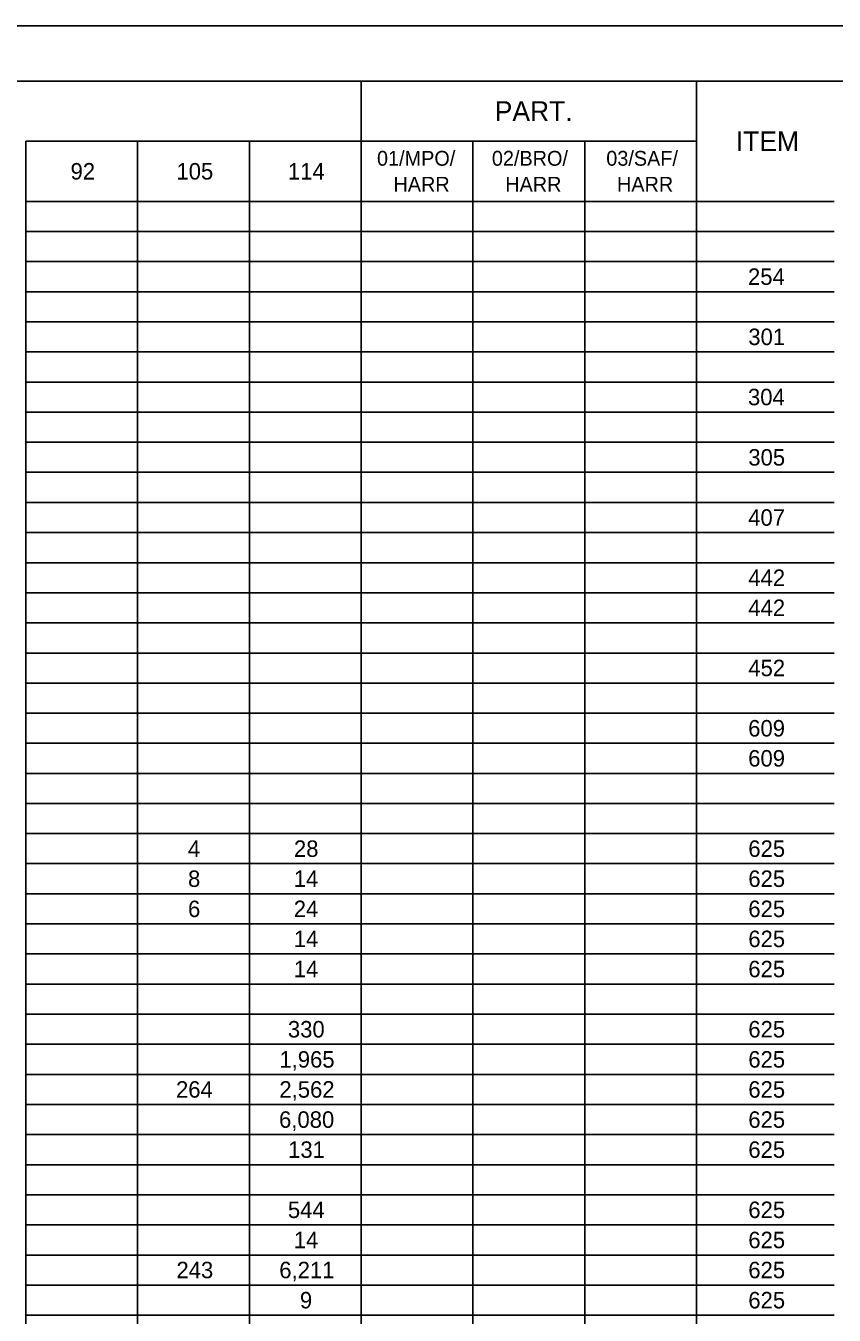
# Model space of a CAD drawing. Extents: x 0 to 34, y 0 to 22.
# Drawn here: x 9.6 to 16.92, y 10.33 to 22 of the extents above; entities that cross this region are included whole.
import ezdxf

# ---------------------------------------------------------------- set-up
doc = ezdxf.new("R2010")
doc.units = 0
for name, color, linetype in [('SH_Border', 7, 'Continuous'), ('SH_Cut_Line', 7, 'Continuous'), ('SH_Text', 7, 'Continuous')]:
    doc.layers.add(name, color=color, linetype=linetype)

msp = doc.modelspace()

# ---------------------------------------------------------------- linework, layer by layer
at = {"layer": 'SH_Border'}
msp.add_lwpolyline([(1.5, 21.5), (33.5, 21.5), (33.5, 0.5), (1.5, 0.5)], close=True, dxfattribs=at)
at = {"layer": 'SH_Cut_Line'}
msp.add_lwpolyline([(0, 0), (34, 0), (34, 22), (0, 22)], close=True, dxfattribs=at)
at = {"layer": 'SH_Text'}
for p, q in [((9.599, 21.5), (11.623, 21.5)), ((11.623, 21.5), (12.636, 21.5)), ((12.636, 21.5), (13.648, 21.5)), ((12.636, 21.5), (12.636, 21.227)), ((13.648, 21.5), (14.66, 21.5)), ((14.66, 21.5), (15.673, 21.5)), ((15.673, 21.5), (16.919, 21.5)), ((15.673, 21.5), (15.673, 21.227)), ((12.636, 21.227), (12.636, 20.955)), ((15.673, 21.227), (15.673, 20.955)), ((9.599, 20.955), (11.623, 20.955)), ((9.599, 20.955), (9.599, 20.682)), ((10.611, 20.955), (10.611, 20.682)), ((11.623, 20.955), (12.636, 20.955)), ((11.623, 20.955), (11.623, 20.682)), ((12.636, 20.955), (13.648, 20.955)), ((12.636, 20.955), (12.636, 20.682)), ((13.648, 20.955), (14.66, 20.955)), ((13.648, 20.955), (13.648, 20.682)), ((14.66, 20.955), (15.673, 20.955)), ((14.66, 20.955), (14.66, 20.682)), ((15.673, 20.955), (15.673, 20.682)), ((9.599, 20.682), (9.599, 20.41)), ((10.611, 20.682), (10.611, 20.41)), ((11.623, 20.682), (11.623, 20.41)), ((12.636, 20.682), (12.636, 20.41)), ((13.648, 20.682), (13.648, 20.41)), ((14.66, 20.682), (14.66, 20.41)), ((15.673, 20.682), (15.673, 20.41)), ((9.599, 20.41), (11.623, 20.41)), ((9.599, 20.41), (9.599, 20.137)), ((10.611, 20.41), (10.611, 20.137)), ((11.623, 20.41), (12.636, 20.41)), ((11.623, 20.41), (11.623, 20.137)), ((12.636, 20.41), (13.648, 20.41)), ((12.636, 20.41), (12.636, 20.137)), ((13.648, 20.41), (14.66, 20.41)), ((13.648, 20.41), (13.648, 20.137)), ((14.66, 20.41), (15.673, 20.41)), ((14.66, 20.41), (14.66, 20.137)), ((15.673, 20.41), (16.919, 20.41)), ((15.673, 20.41), (15.673, 20.137)), ((9.599, 20.137), (11.623, 20.137)), ((9.599, 20.137), (9.599, 18.774)), ((10.611, 20.137), (10.611, 18.774)), ((11.623, 20.137), (12.636, 20.137)), ((11.623, 20.137), (11.623, 18.774)), ((12.636, 20.137), (13.648, 20.137)), ((12.636, 20.137), (12.636, 18.774)), ((13.648, 20.137), (14.66, 20.137)), ((13.648, 20.137), (13.648, 18.774)), ((14.66, 20.137), (15.673, 20.137)), ((14.66, 20.137), (14.66, 18.774)), ((15.673, 20.137), (16.919, 20.137)), ((15.673, 20.137), (15.673, 18.774)), ((9.599, 19.865), (11.623, 19.865)), ((11.623, 19.865), (12.636, 19.865)), ((12.636, 19.865), (13.648, 19.865)), ((13.648, 19.865), (14.66, 19.865)), ((14.66, 19.865), (15.673, 19.865)), ((15.673, 19.865), (16.919, 19.865)), ((9.599, 19.592), (11.623, 19.592)), ((11.623, 19.592), (12.636, 19.592)), ((12.636, 19.592), (13.648, 19.592)), ((13.648, 19.592), (14.66, 19.592)), ((14.66, 19.592), (15.673, 19.592)), ((15.673, 19.592), (16.919, 19.592)), ((9.599, 19.32), (11.623, 19.32)), ((11.623, 19.32), (12.636, 19.32)), ((12.636, 19.32), (13.648, 19.32)), ((13.648, 19.32), (14.66, 19.32)), ((14.66, 19.32), (15.673, 19.32)), ((15.673, 19.32), (16.919, 19.32)), ((9.599, 19.047), (11.623, 19.047)), ((11.623, 19.047), (12.636, 19.047)), ((12.636, 19.047), (13.648, 19.047)), ((13.648, 19.047), (14.66, 19.047)), ((14.66, 19.047), (15.673, 19.047)), ((15.673, 19.047), (16.919, 19.047)), ((9.599, 18.774), (11.623, 18.774)), ((9.599, 18.774), (9.599, 18.229)), ((10.611, 18.774), (10.611, 18.229)), ((11.623, 18.774), (12.636, 18.774)), ((11.623, 18.774), (11.623, 18.229)), ((12.636, 18.774), (13.648, 18.774)), ((12.636, 18.774), (12.636, 18.229)), ((13.648, 18.774), (14.66, 18.774)), ((13.648, 18.774), (13.648, 18.229)), ((14.66, 18.774), (15.673, 18.774)), ((14.66, 18.774), (14.66, 18.229)), ((15.673, 18.774), (16.919, 18.774)), ((15.673, 18.774), (15.673, 18.229)), ((9.599, 18.502), (11.623, 18.502)), ((11.623, 18.502), (12.636, 18.502)), ((12.636, 18.502), (13.648, 18.502)), ((13.648, 18.502), (14.66, 18.502)), ((14.66, 18.502), (15.673, 18.502)), ((15.673, 18.502), (16.919, 18.502)), ((9.599, 18.229), (11.623, 18.229)), ((9.599, 18.229), (9.599, 17.957)), ((10.611, 18.229), (10.611, 17.957)), ((11.623, 18.229), (12.636, 18.229)), ((11.623, 18.229), (11.623, 17.957)), ((12.636, 18.229), (13.648, 18.229)), ((12.636, 18.229), (12.636, 17.957)), ((13.648, 18.229), (14.66, 18.229)), ((13.648, 18.229), (13.648, 17.957)), ((14.66, 18.229), (15.673, 18.229)), ((14.66, 18.229), (14.66, 17.957)), ((15.673, 18.229), (16.919, 18.229)), ((15.673, 18.229), (15.673, 17.957)), ((9.599, 17.957), (11.623, 17.957)), ((9.599, 17.957), (9.599, 17.684)), ((10.611, 17.957), (10.611, 17.684)), ((11.623, 17.957), (12.636, 17.957)), ((11.623, 17.957), (11.623, 17.684)), ((12.636, 17.957), (13.648, 17.957)), ((12.636, 17.957), (12.636, 17.684)), ((13.648, 17.957), (14.66, 17.957)), ((13.648, 17.957), (13.648, 17.684)), ((14.66, 17.957), (15.673, 17.957)), ((14.66, 17.957), (14.66, 17.684)), ((15.673, 17.957), (16.919, 17.957)), ((15.673, 17.957), (15.673, 17.684)), ((9.599, 17.684), (11.623, 17.684)), ((9.599, 17.684), (9.599, 17.412)), ((10.611, 17.684), (10.611, 17.412)), ((11.623, 17.684), (12.636, 17.684)), ((11.623, 17.684), (11.623, 17.412)), ((12.636, 17.684), (13.648, 17.684)), ((12.636, 17.684), (12.636, 17.412)), ((13.648, 17.684), (14.66, 17.684)), ((13.648, 17.684), (13.648, 17.412)), ((14.66, 17.684), (15.673, 17.684)), ((14.66, 17.684), (14.66, 17.412)), ((15.673, 17.684), (16.919, 17.684)), ((15.673, 17.684), (15.673, 17.412)), ((9.599, 17.412), (11.623, 17.412)), ((9.599, 17.412), (9.599, 17.139)), ((10.611, 17.412), (10.611, 17.139)), ((11.623, 17.412), (12.636, 17.412)), ((11.623, 17.412), (11.623, 17.139)), ((12.636, 17.412), (13.648, 17.412)), ((12.636, 17.412), (12.636, 17.139)), ((13.648, 17.412), (14.66, 17.412)), ((13.648, 17.412), (13.648, 17.139)), ((14.66, 17.412), (15.673, 17.412)), ((14.66, 17.412), (14.66, 17.139)), ((15.673, 17.412), (16.919, 17.412)), ((15.673, 17.412), (15.673, 17.139)), ((9.599, 17.139), (11.623, 17.139)), ((9.599, 17.139), (9.599, 16.867)), ((10.611, 17.139), (10.611, 16.867)), ((11.623, 17.139), (12.636, 17.139)), ((11.623, 17.139), (11.623, 16.867)), ((12.636, 17.139), (13.648, 17.139)), ((12.636, 17.139), (12.636, 16.867)), ((13.648, 17.139), (14.66, 17.139)), ((13.648, 17.139), (13.648, 16.867)), ((14.66, 17.139), (15.673, 17.139)), ((14.66, 17.139), (14.66, 16.867)), ((15.673, 17.139), (16.919, 17.139)), ((15.673, 17.139), (15.673, 16.867)), ((9.599, 16.867), (11.623, 16.867)), ((9.599, 16.867), (9.599, 16.321)), ((10.611, 16.867), (10.611, 16.321)), ((11.623, 16.867), (12.636, 16.867)), ((11.623, 16.867), (11.623, 16.321)), ((12.636, 16.867), (13.648, 16.867)), ((12.636, 16.867), (12.636, 16.321)), ((13.648, 16.867), (14.66, 16.867)), ((13.648, 16.867), (13.648, 16.321)), ((14.66, 16.867), (15.673, 16.867)), ((14.66, 16.867), (14.66, 16.321)), ((15.673, 16.867), (16.919, 16.867)), ((15.673, 16.867), (15.673, 16.321)), ((9.599, 16.594), (11.623, 16.594)), ((11.623, 16.594), (12.636, 16.594)), ((12.636, 16.594), (13.648, 16.594)), ((13.648, 16.594), (14.66, 16.594)), ((14.66, 16.594), (15.673, 16.594)), ((15.673, 16.594), (16.919, 16.594)), ((9.599, 16.321), (11.623, 16.321)), ((9.599, 16.321), (9.599, 16.049)), ((10.611, 16.321), (10.611, 16.049)), ((11.623, 16.321), (12.636, 16.321)), ((11.623, 16.321), (11.623, 16.049)), ((12.636, 16.321), (13.648, 16.321)), ((12.636, 16.321), (12.636, 16.049)), ((13.648, 16.321), (14.66, 16.321)), ((13.648, 16.321), (13.648, 16.049)), ((14.66, 16.321), (15.673, 16.321)), ((14.66, 16.321), (14.66, 16.049)), ((15.673, 16.321), (16.919, 16.321)), ((15.673, 16.321), (15.673, 16.049)), ((9.599, 16.049), (11.623, 16.049)), ((9.599, 16.049), (9.599, 15.776)), ((10.611, 16.049), (10.611, 15.776)), ((11.623, 16.049), (12.636, 16.049)), ((11.623, 16.049), (11.623, 15.776)), ((12.636, 16.049), (13.648, 16.049)), ((12.636, 16.049), (12.636, 15.776)), ((13.648, 16.049), (14.66, 16.049)), ((13.648, 16.049), (13.648, 15.776)), ((14.66, 16.049), (15.673, 16.049)), ((14.66, 16.049), (14.66, 15.776)), ((15.673, 16.049), (16.919, 16.049)), ((15.673, 16.049), (15.673, 15.776)), ((9.599, 15.776), (11.623, 15.776)), ((9.599, 15.776), (9.599, 15.504)), ((10.611, 15.776), (10.611, 15.504)), ((11.623, 15.776), (12.636, 15.776)), ((11.623, 15.776), (11.623, 15.504)), ((12.636, 15.776), (13.648, 15.776)), ((12.636, 15.776), (12.636, 15.504)), ((13.648, 15.776), (14.66, 15.776)), ((13.648, 15.776), (13.648, 15.504)), ((14.66, 15.776), (15.673, 15.776)), ((14.66, 15.776), (14.66, 15.504)), ((15.673, 15.776), (16.919, 15.776)), ((15.673, 15.776), (15.673, 15.504)), ((9.599, 15.504), (11.623, 15.504)), ((9.599, 15.504), (9.599, 14.959)), ((10.611, 15.504), (10.611, 14.959)), ((11.623, 15.504), (12.636, 15.504)), ((11.623, 15.504), (11.623, 14.959)), ((12.636, 15.504), (13.648, 15.504)), ((12.636, 15.504), (12.636, 14.959)), ((13.648, 15.504), (14.66, 15.504)), ((13.648, 15.504), (13.648, 14.959)), ((14.66, 15.504), (15.673, 15.504)), ((14.66, 15.504), (14.66, 14.959)), ((15.673, 15.504), (16.919, 15.504)), ((15.673, 15.504), (15.673, 14.959)), ((9.599, 15.231), (11.623, 15.231)), ((11.623, 15.231), (12.636, 15.231)), ((12.636, 15.231), (13.648, 15.231)), ((13.648, 15.231), (14.66, 15.231)), ((14.66, 15.231), (15.673, 15.231)), ((15.673, 15.231), (16.919, 15.231)), ((9.599, 14.959), (11.623, 14.959)), ((9.599, 14.959), (9.599, 14.686)), ((10.611, 14.959), (10.611, 14.686)), ((11.623, 14.959), (12.636, 14.959)), ((11.623, 14.959), (11.623, 14.686)), ((12.636, 14.959), (13.648, 14.959)), ((12.636, 14.959), (12.636, 14.686)), ((13.648, 14.959), (14.66, 14.959)), ((13.648, 14.959), (13.648, 14.686)), ((14.66, 14.959), (15.673, 14.959)), ((14.66, 14.959), (14.66, 14.686)), ((15.673, 14.959), (16.919, 14.959)), ((15.673, 14.959), (15.673, 14.686)), ((9.599, 14.686), (11.623, 14.686)), ((9.599, 14.686), (9.599, 14.414)), ((10.611, 14.686), (10.611, 14.414)), ((11.623, 14.686), (12.636, 14.686)), ((11.623, 14.686), (11.623, 14.414)), ((12.636, 14.686), (13.648, 14.686)), ((12.636, 14.686), (12.636, 14.414)), ((13.648, 14.686), (14.66, 14.686)), ((13.648, 14.686), (13.648, 14.414)), ((14.66, 14.686), (15.673, 14.686)), ((14.66, 14.686), (14.66, 14.414)), ((15.673, 14.686), (16.919, 14.686)), ((15.673, 14.686), (15.673, 14.414)), ((9.599, 14.414), (11.623, 14.414)), ((9.599, 14.414), (9.599, 14.141)), ((10.611, 14.414), (10.611, 14.141)), ((11.623, 14.414), (12.636, 14.414)), ((11.623, 14.414), (11.623, 14.141)), ((12.636, 14.414), (13.648, 14.414)), ((12.636, 14.414), (12.636, 14.141)), ((13.648, 14.414), (14.66, 14.414)), ((13.648, 14.414), (13.648, 14.141)), ((14.66, 14.414), (15.673, 14.414)), ((14.66, 14.414), (14.66, 14.141)), ((15.673, 14.414), (16.919, 14.414)), ((15.673, 14.414), (15.673, 14.141)), ((9.599, 14.141), (11.623, 14.141)), ((9.599, 14.141), (9.599, 11.961)), ((10.611, 14.141), (10.611, 11.961)), ((11.623, 14.141), (12.636, 14.141)), ((11.623, 14.141), (11.623, 11.961)), ((12.636, 14.141), (13.648, 14.141)), ((12.636, 14.141), (12.636, 11.961)), ((13.648, 14.141), (14.66, 14.141)), ((13.648, 14.141), (13.648, 11.961)), ((14.66, 14.141), (15.673, 14.141)), ((14.66, 14.141), (14.66, 11.961)), ((15.673, 14.141), (16.919, 14.141)), ((15.673, 14.141), (15.673, 11.961)), ((9.599, 13.869), (11.623, 13.869)), ((11.623, 13.869), (12.636, 13.869)), ((12.636, 13.869), (13.648, 13.869)), ((13.648, 13.869), (14.66, 13.869)), ((14.66, 13.869), (15.673, 13.869)), ((15.673, 13.869), (16.919, 13.869)), ((9.599, 13.596), (11.623, 13.596)), ((11.623, 13.596), (12.636, 13.596)), ((12.636, 13.596), (13.648, 13.596)), ((13.648, 13.596), (14.66, 13.596)), ((14.66, 13.596), (15.673, 13.596)), ((15.673, 13.596), (16.919, 13.596)), ((9.599, 13.323), (11.623, 13.323)), ((11.623, 13.323), (12.636, 13.323)), ((12.636, 13.323), (13.648, 13.323)), ((13.648, 13.323), (14.66, 13.323)), ((14.66, 13.323), (15.673, 13.323)), ((15.673, 13.323), (16.919, 13.323)), ((9.599, 13.051), (11.623, 13.051)), ((11.623, 13.051), (12.636, 13.051)), ((12.636, 13.051), (13.648, 13.051)), ((13.648, 13.051), (14.66, 13.051)), ((14.66, 13.051), (15.673, 13.051)), ((15.673, 13.051), (16.919, 13.051)), ((9.599, 12.778), (11.623, 12.778)), ((11.623, 12.778), (12.636, 12.778)), ((12.636, 12.778), (13.648, 12.778)), ((13.648, 12.778), (14.66, 12.778)), ((14.66, 12.778), (15.673, 12.778)), ((15.673, 12.778), (16.919, 12.778)), ((9.599, 12.506), (11.623, 12.506)), ((11.623, 12.506), (12.636, 12.506)), ((12.636, 12.506), (13.648, 12.506)), ((13.648, 12.506), (14.66, 12.506)), ((14.66, 12.506), (15.673, 12.506)), ((15.673, 12.506), (16.919, 12.506)), ((9.599, 12.233), (11.623, 12.233)), ((11.623, 12.233), (12.636, 12.233)), ((12.636, 12.233), (13.648, 12.233)), ((13.648, 12.233), (14.66, 12.233)), ((14.66, 12.233), (15.673, 12.233)), ((15.673, 12.233), (16.919, 12.233)), ((9.599, 11.961), (11.623, 11.961)), ((9.599, 11.961), (9.599, 11.688)), ((10.611, 11.961), (10.611, 11.688)), ((11.623, 11.961), (12.636, 11.961)), ((11.623, 11.961), (11.623, 11.688)), ((12.636, 11.961), (13.648, 11.961)), ((12.636, 11.961), (12.636, 11.688)), ((13.648, 11.961), (14.66, 11.961)), ((13.648, 11.961), (13.648, 11.688)), ((14.66, 11.961), (15.673, 11.961)), ((14.66, 11.961), (14.66, 11.688)), ((15.673, 11.961), (16.919, 11.961)), ((15.673, 11.961), (15.673, 11.688)), ((9.599, 11.688), (11.623, 11.688)), ((9.599, 11.688), (9.599, 10.598)), ((10.611, 11.688), (10.611, 10.598)), ((11.623, 11.688), (12.636, 11.688)), ((11.623, 11.688), (11.623, 10.598)), ((12.636, 11.688), (13.648, 11.688)), ((12.636, 11.688), (12.636, 10.598)), ((13.648, 11.688), (14.66, 11.688)), ((13.648, 11.688), (13.648, 10.598)), ((14.66, 11.688), (15.673, 11.688)), ((14.66, 11.688), (14.66, 10.598)), ((15.673, 11.688), (16.919, 11.688)), ((15.673, 11.688), (15.673, 10.598)), ((9.599, 11.416), (11.623, 11.416)), ((11.623, 11.416), (12.636, 11.416)), ((12.636, 11.416), (13.648, 11.416)), ((13.648, 11.416), (14.66, 11.416)), ((14.66, 11.416), (15.673, 11.416)), ((15.673, 11.416), (16.919, 11.416)), ((9.599, 11.143), (11.623, 11.143)), ((11.623, 11.143), (12.636, 11.143)), ((12.636, 11.143), (13.648, 11.143)), ((13.648, 11.143), (14.66, 11.143)), ((14.66, 11.143), (15.673, 11.143)), ((15.673, 11.143), (16.919, 11.143)), ((9.599, 10.87), (11.623, 10.87)), ((11.623, 10.87), (12.636, 10.87)), ((12.636, 10.87), (13.648, 10.87)), ((13.648, 10.87), (14.66, 10.87)), ((14.66, 10.87), (15.673, 10.87)), ((15.673, 10.87), (16.919, 10.87)), ((9.599, 10.598), (11.623, 10.598)), ((9.599, 10.598), (9.599, 10.325)), ((10.611, 10.598), (10.611, 10.325)), ((11.623, 10.598), (12.636, 10.598)), ((11.623, 10.598), (11.623, 10.325)), ((12.636, 10.598), (13.648, 10.598)), ((12.636, 10.598), (12.636, 10.325)), ((13.648, 10.598), (14.66, 10.598)), ((13.648, 10.598), (13.648, 10.325)), ((14.66, 10.598), (15.673, 10.598)), ((14.66, 10.598), (14.66, 10.325)), ((15.673, 10.598), (16.919, 10.598)), ((15.673, 10.598), (15.673, 10.325)), ((9.599, 10.325), (11.623, 10.325)), ((9.599, 10.325), (9.599, 10.053)), ((10.611, 10.325), (10.611, 10.053)), ((11.623, 10.325), (12.636, 10.325)), ((11.623, 10.325), (11.623, 10.053)), ((12.636, 10.325), (13.648, 10.325)), ((12.636, 10.325), (12.636, 10.053)), ((13.648, 10.325), (14.66, 10.325)), ((13.648, 10.325), (13.648, 10.053)), ((14.66, 10.325), (15.673, 10.325)), ((14.66, 10.325), (14.66, 10.053)), ((15.673, 10.325), (16.919, 10.325)), ((15.673, 10.325), (15.673, 10.053))]:
    msp.add_line(p, q, dxfattribs=at)

# ---------------------------------------------------------------- texts
for s, height, p in [('PART.', 0.1791, (13.845, 21.138)), ('ITEM', 0.1791, (16.028, 20.865)), ('01/MPO/', 0.1343, (12.779, 20.733)), ('02/BRO/', 0.1343, (13.819, 20.733)), ('03/SAF/', 0.1343, (14.855, 20.733)), ('92', 0.1493, (10.004, 20.608)), ('105', 0.1493, (10.963, 20.608)), ('114', 0.1493, (11.972, 20.608)), ('HARR', 0.1343, (12.928, 20.498)), ('HARR', 0.1343, (13.94, 20.498)), ('HARR', 0.1343, (14.952, 20.498)), ('254', 0.1493, (16.138, 19.654)), ('301', 0.1493, (16.141, 19.109)), ('304', 0.1493, (16.138, 18.564)), ('305', 0.1493, (16.141, 18.018)), ('407', 0.1493, (16.14, 17.473)), ('442', 0.1493, (16.141, 16.928)), ('442', 0.1493, (16.141, 16.656)), ('452', 0.1493, (16.141, 16.111)), ('609', 0.1493, (16.14, 15.565)), ('609', 0.1493, (16.14, 15.293)), ('4', 0.149, (11.067, 14.475)), ('28', 0.1493, (12.027, 14.475)), ('625', 0.1493, (16.141, 14.475)), ('8', 0.149, (11.068, 14.203)), ('14', 0.1493, (12.025, 14.203)), ('625', 0.1493, (16.141, 14.203)), ('6', 0.149, (11.068, 13.93)), ('24', 0.1493, (12.025, 13.93)), ('625', 0.1493, (16.141, 13.93)), ('14', 0.1493, (12.025, 13.658)), ('625', 0.1493, (16.141, 13.658)), ('14', 0.1493, (12.025, 13.385)), ('625', 0.1493, (16.141, 13.385)), ('330', 0.1493, (11.972, 12.84)), ('625', 0.1493, (16.141, 12.84)), ('1,965', 0.1493, (11.895, 12.567)), ('625', 0.1493, (16.141, 12.567)), ('264', 0.1493, (10.959, 12.295)), ('2,562', 0.1493, (11.895, 12.295)), ('625', 0.1493, (16.141, 12.295)), ('6,080', 0.1493, (11.892, 12.022)), ('625', 0.1493, (16.141, 12.022)), ('131', 0.1493, (11.974, 11.75)), ('625', 0.1493, (16.141, 11.75)), ('544', 0.1493, (11.972, 11.205)), ('625', 0.1493, (16.141, 11.205)), ('14', 0.1493, (12.025, 10.932)), ('625', 0.1493, (16.141, 10.932)), ('243', 0.1493, (10.963, 10.66)), ('6,211', 0.1493, (11.894, 10.66)), ('625', 0.1493, (16.141, 10.66)), ('9', 0.149, (12.081, 10.387)), ('625', 0.1493, (16.141, 10.387))]:
    msp.add_text(s, height=height, dxfattribs=at).set_placement(p)

doc.saveas('drawing.dxf')
